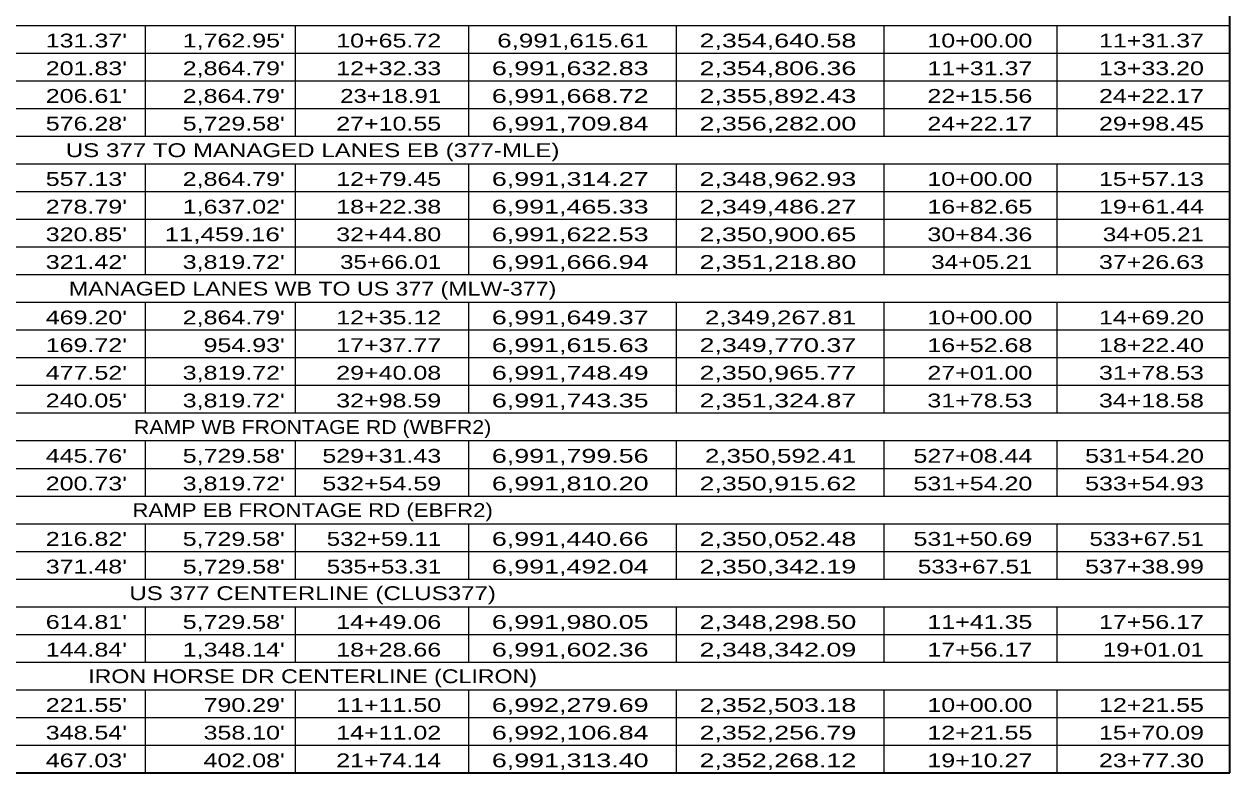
# Model space of a CAD drawing. Extents: x 1953053 to 1967065, y 7363860 to 7371201.
# Drawn here: x 1960635 to 1961680, y 7368112 to 7368761 of the extents above; entities that cross this region are included whole.
import ezdxf
from ezdxf.enums import TextEntityAlignment as Align

# ---------------------------------------------------------------- set-up
doc = ezdxf.new("R2010")
doc.units = 0
doc.header["$LTSCALE"] = 4.8
doc.layers.add('10', color=7, linetype='Continuous')
doc.layers.add('12', color=7, linetype='Continuous', lineweight=25)

msp = doc.modelspace()

# ---------------------------------------------------------------- linework, layer by layer
at = {"layer": '12', "lineweight": 35}
for p, q in [((1961680.213, 7368159.747), (1961680.213, 7370164.879)), ((1961680.213, 7368111.747), (1961680.213, 7370116.879)), ((1959956.881, 7368111.747), (1961680.213, 7368111.747))]:
    msp.add_line(p, q, dxfattribs=at)
at = {"layer": '12', "lineweight": 13}
for p, q in [((1959956.881, 7368759.747), (1961680.213, 7368759.747)), ((1959956.881, 7368735.747), (1961680.213, 7368735.747)), ((1959956.881, 7368711.747), (1961680.213, 7368711.747)), ((1959956.881, 7368687.747), (1961680.213, 7368687.747)), ((1959956.881, 7368663.747), (1961680.213, 7368663.747)), ((1959956.881, 7368639.747), (1961680.213, 7368639.747)), ((1959956.881, 7368615.747), (1961680.213, 7368615.747)), ((1959956.881, 7368591.747), (1961680.213, 7368591.747)), ((1959956.881, 7368567.747), (1961680.213, 7368567.747)), ((1959956.881, 7368543.747), (1961680.213, 7368543.747)), ((1959956.881, 7368519.747), (1961680.213, 7368519.747)), ((1959956.881, 7368495.747), (1961680.213, 7368495.747)), ((1959956.881, 7368471.747), (1961680.213, 7368471.747)), ((1959956.881, 7368447.747), (1961680.213, 7368447.747)), ((1959956.881, 7368423.747), (1961680.213, 7368423.747)), ((1959956.881, 7368399.747), (1961680.213, 7368399.747)), ((1959956.881, 7368375.747), (1961680.213, 7368375.747)), ((1959956.881, 7368351.747), (1961680.213, 7368351.747)), ((1959956.881, 7368327.747), (1961680.213, 7368327.747)), ((1959956.881, 7368303.747), (1961680.213, 7368303.747)), ((1959956.881, 7368279.747), (1961680.213, 7368279.747)), ((1959956.881, 7368255.747), (1961680.213, 7368255.747)), ((1959956.881, 7368231.747), (1961680.213, 7368231.747)), ((1959956.881, 7368207.747), (1961680.213, 7368207.747)), ((1959956.881, 7368207.747), (1961680.213, 7368207.747)), ((1959956.881, 7368183.747), (1961680.213, 7368183.747)), ((1959956.881, 7368183.747), (1961680.213, 7368183.747)), ((1959956.881, 7368159.747), (1961680.213, 7368159.747)), ((1959956.881, 7368135.747), (1961680.213, 7368135.747)), ((1959956.881, 7368111.747), (1961680.213, 7368111.747))]:
    msp.add_line(p, q, dxfattribs=at)
at = {"layer": '12'}
for p, q in [((1960740.213, 7368759.747), (1960740.213, 7368663.747)), ((1960870.213, 7368759.747), (1960870.213, 7368663.747)), ((1961020.213, 7368759.747), (1961020.213, 7368663.747)), ((1961200.213, 7368759.747), (1961200.213, 7368663.747)), ((1961380.213, 7368759.747), (1961380.213, 7368663.747)), ((1961530.213, 7368759.747), (1961530.213, 7368663.747)), ((1960740.213, 7368639.747), (1960740.213, 7368543.747)), ((1960870.213, 7368639.747), (1960870.213, 7368543.747)), ((1961020.213, 7368639.747), (1961020.213, 7368543.747)), ((1961200.213, 7368639.747), (1961200.213, 7368543.747)), ((1961380.213, 7368639.747), (1961380.213, 7368543.747)), ((1961530.213, 7368639.747), (1961530.213, 7368543.747)), ((1960740.213, 7368519.747), (1960740.213, 7368423.747)), ((1960870.213, 7368519.747), (1960870.213, 7368423.747)), ((1961020.213, 7368519.747), (1961020.213, 7368423.747)), ((1961200.213, 7368519.747), (1961200.213, 7368423.747)), ((1961380.213, 7368519.747), (1961380.213, 7368423.747)), ((1961530.213, 7368519.747), (1961530.213, 7368423.747)), ((1960740.213, 7368399.747), (1960740.213, 7368351.747)), ((1960870.213, 7368399.747), (1960870.213, 7368351.747)), ((1961020.213, 7368399.747), (1961020.213, 7368351.747)), ((1961200.213, 7368399.747), (1961200.213, 7368351.747)), ((1961380.213, 7368399.747), (1961380.213, 7368351.747)), ((1961530.213, 7368399.747), (1961530.213, 7368351.747)), ((1960740.213, 7368327.747), (1960740.213, 7368279.747)), ((1960870.213, 7368327.747), (1960870.213, 7368279.747)), ((1961020.213, 7368327.747), (1961020.213, 7368279.747)), ((1961200.213, 7368327.747), (1961200.213, 7368279.747)), ((1961380.213, 7368327.747), (1961380.213, 7368279.747)), ((1961530.213, 7368327.747), (1961530.213, 7368279.747)), ((1960740.213, 7368255.747), (1960740.213, 7368207.747)), ((1960870.213, 7368255.747), (1960870.213, 7368207.747)), ((1961020.213, 7368255.747), (1961020.213, 7368207.747)), ((1961200.213, 7368255.747), (1961200.213, 7368207.747)), ((1961380.213, 7368255.747), (1961380.213, 7368207.747)), ((1961530.213, 7368255.747), (1961530.213, 7368207.747)), ((1960740.213, 7368183.747), (1960740.213, 7368111.747)), ((1960870.213, 7368183.747), (1960870.213, 7368111.747)), ((1961020.213, 7368183.747), (1961020.213, 7368111.747)), ((1961200.213, 7368183.747), (1961200.213, 7368111.747)), ((1961380.213, 7368183.747), (1961380.213, 7368111.747)), ((1961530.213, 7368183.747), (1961530.213, 7368111.747))]:
    msp.add_line(p, q, dxfattribs=at)

# ---------------------------------------------------------------- texts
at = {"layer": '10'}
for s, width, p in [("131.37'", 1.35, (1960724.337, 7368740.574)), ("1,762.95'", 1.35, (1960861.106, 7368740.574)), ('10+65.72', 1.35, (1960996.65, 7368740.574)), ('6,991,615.61', 1.4, (1961176.415, 7368740.574)), ('2,354,640.58', 1.45, (1961356.415, 7368740.574)), ('10+00.00', 1.35, (1961508.993, 7368740.574)), ('11+31.37', 1.35, (1961657.725, 7368740.574)), ("201.83'", 1.35, (1960724.337, 7368716.574)), ("2,864.79'", 1.35, (1960861.106, 7368716.574)), ('12+32.33', 1.35, (1960996.65, 7368716.574)), ('6,991,632.83', 1.45, (1961176.415, 7368716.574)), ('2,354,806.36', 1.45, (1961356.415, 7368716.574)), ('11+31.37', 1.35, (1961508.993, 7368716.574)), ('13+33.20', 1.35, (1961657.725, 7368716.574)), ("206.61'", 1.35, (1960724.337, 7368692.574)), ("2,864.79'", 1.35, (1960861.106, 7368692.574)), ('23+18.91', 1.3, (1960996.65, 7368692.574)), ('6,991,668.72', 1.45, (1961176.415, 7368692.574)), ('2,355,892.43', 1.45, (1961356.415, 7368692.574)), ('22+15.56', 1.35, (1961508.993, 7368692.574)), ('24+22.17', 1.35, (1961657.725, 7368692.574)), ("576.28'", 1.35, (1960724.337, 7368668.574)), ("5,729.58'", 1.35, (1960861.106, 7368668.574)), ('27+10.55', 1.35, (1960996.65, 7368668.574)), ('6,991,709.84', 1.45, (1961176.415, 7368668.574)), ('2,356,282.00', 1.45, (1961356.415, 7368668.574)), ('24+22.17', 1.35, (1961508.993, 7368668.574)), ('29+98.45', 1.35, (1961657.725, 7368668.574)), ("557.13'", 1.35, (1960724.337, 7368620.574)), ("2,864.79'", 1.35, (1960861.106, 7368620.574)), ('12+79.45', 1.35, (1960996.65, 7368620.574)), ('6,991,314.27', 1.45, (1961176.415, 7368620.574)), ('2,348,962.93', 1.45, (1961356.415, 7368620.574)), ('10+00.00', 1.35, (1961508.993, 7368620.574)), ('15+57.13', 1.35, (1961657.725, 7368620.574)), ("278.79'", 1.35, (1960724.337, 7368596.574)), ("1,637.02'", 1.35, (1960861.106, 7368596.574)), ('18+22.38', 1.35, (1960996.65, 7368596.574)), ('6,991,465.33', 1.45, (1961176.415, 7368596.574)), ('2,349,486.27', 1.45, (1961356.415, 7368596.574)), ('16+82.65', 1.35, (1961508.993, 7368596.574)), ('19+61.44', 1.35, (1961657.725, 7368596.574)), ("320.85'", 1.35, (1960724.337, 7368572.574)), ("11,459.16'", 1.4, (1960861.106, 7368572.574)), ('32+44.80', 1.35, (1960996.65, 7368572.574)), ('6,991,622.53', 1.45, (1961176.415, 7368572.574)), ('2,350,900.65', 1.45, (1961356.415, 7368572.574)), ('30+84.36', 1.35, (1961508.993, 7368572.574)), ('34+05.21', 1.3, (1961657.725, 7368572.574)), ("321.42'", 1.35, (1960724.337, 7368548.574)), ("3,819.72'", 1.35, (1960861.106, 7368548.574)), ('35+66.01', 1.3, (1960996.65, 7368548.574)), ('6,991,666.94', 1.45, (1961176.415, 7368548.574)), ('2,351,218.80', 1.45, (1961356.415, 7368548.574)), ('34+05.21', 1.3, (1961508.993, 7368548.574)), ('37+26.63', 1.35, (1961657.725, 7368548.574)), ("469.20'", 1.35, (1960724.337, 7368500.574)), ("2,864.79'", 1.35, (1960861.106, 7368500.574)), ('12+35.12', 1.35, (1960996.65, 7368500.574)), ('6,991,649.37', 1.45, (1961176.415, 7368500.574)), ('2,349,267.81', 1.4, (1961356.415, 7368500.574)), ('10+00.00', 1.35, (1961508.993, 7368500.574)), ('14+69.20', 1.35, (1961657.725, 7368500.574)), ("169.72'", 1.35, (1960724.337, 7368476.574)), ("954.93'", 1.35, (1960861.106, 7368476.574)), ('17+37.77', 1.35, (1960996.65, 7368476.574)), ('6,991,615.63', 1.45, (1961176.415, 7368476.574)), ('2,349,770.37', 1.45, (1961356.415, 7368476.574)), ('16+52.68', 1.35, (1961508.993, 7368476.574)), ('18+22.40', 1.35, (1961657.725, 7368476.574)), ("477.52'", 1.35, (1960724.337, 7368452.574)), ("3,819.72'", 1.35, (1960861.106, 7368452.574)), ('29+40.08', 1.35, (1960996.65, 7368452.574)), ('6,991,748.49', 1.45, (1961176.415, 7368452.574)), ('2,350,965.77', 1.45, (1961356.415, 7368452.574)), ('27+01.00', 1.35, (1961508.993, 7368452.574)), ('31+78.53', 1.35, (1961657.725, 7368452.574)), ("240.05'", 1.35, (1960724.337, 7368428.574)), ("3,819.72'", 1.35, (1960861.106, 7368428.574)), ('32+98.59', 1.35, (1960996.65, 7368428.574)), ('6,991,743.35', 1.45, (1961176.415, 7368428.574)), ('2,351,324.87', 1.45, (1961356.415, 7368428.574)), ('31+78.53', 1.35, (1961508.993, 7368428.574)), ('34+18.58', 1.35, (1961657.725, 7368428.574)), ("445.76'", 1.35, (1960724.337, 7368380.574)), ("5,729.58'", 1.35, (1960861.106, 7368380.574)), ('529+31.43', 1.35, (1960996.65, 7368380.574)), ('6,991,799.56', 1.45, (1961176.415, 7368380.574)), ('2,350,592.41', 1.4, (1961356.415, 7368380.574)), ('527+08.44', 1.35, (1961508.993, 7368380.574)), ('531+54.20', 1.35, (1961657.725, 7368380.574)), ("200.73'", 1.35, (1960724.337, 7368356.574)), ("3,819.72'", 1.35, (1960861.106, 7368356.574)), ('532+54.59', 1.35, (1960996.65, 7368356.574)), ('6,991,810.20', 1.45, (1961176.415, 7368356.574)), ('2,350,915.62', 1.45, (1961356.415, 7368356.574)), ('531+54.20', 1.35, (1961508.993, 7368356.574)), ('533+54.93', 1.35, (1961657.725, 7368356.574)), ("216.82'", 1.35, (1960724.337, 7368308.574)), ("5,729.58'", 1.35, (1960861.106, 7368308.574)), ('532+59.11', 1.3, (1960996.65, 7368308.574)), ('6,991,440.66', 1.45, (1961176.415, 7368308.574)), ('2,350,052.48', 1.45, (1961356.415, 7368308.574)), ('531+50.69', 1.35, (1961508.993, 7368308.574)), ('533+67.51', 1.3, (1961657.725, 7368308.574)), ("371.48'", 1.35, (1960724.337, 7368284.574)), ("5,729.58'", 1.35, (1960861.106, 7368284.574)), ('535+53.31', 1.3, (1960996.65, 7368284.574)), ('6,991,492.04', 1.45, (1961176.415, 7368284.574)), ('2,350,342.19', 1.45, (1961356.415, 7368284.574)), ('533+67.51', 1.3, (1961508.993, 7368284.574)), ('537+38.99', 1.35, (1961657.725, 7368284.574)), ("614.81'", 1.35, (1960724.337, 7368236.574)), ("5,729.58'", 1.35, (1960861.106, 7368236.574)), ('14+49.06', 1.35, (1960996.65, 7368236.574)), ('6,991,980.05', 1.45, (1961176.415, 7368236.574)), ('2,348,298.50', 1.45, (1961356.415, 7368236.574)), ('11+41.35', 1.35, (1961508.993, 7368236.574)), ('17+56.17', 1.35, (1961657.725, 7368236.574)), ("144.84'", 1.35, (1960724.337, 7368212.574)), ("1,348.14'", 1.35, (1960861.106, 7368212.574)), ('18+28.66', 1.35, (1960996.65, 7368212.574)), ('6,991,602.36', 1.45, (1961176.415, 7368212.574)), ('2,348,342.09', 1.45, (1961356.415, 7368212.574)), ('17+56.17', 1.35, (1961508.993, 7368212.574)), ('19+01.01', 1.3, (1961657.725, 7368212.574)), ("221.55'", 1.35, (1960724.337, 7368164.574)), ("790.29'", 1.35, (1960861.106, 7368164.574)), ('11+11.50', 1.35, (1960996.65, 7368164.574)), ('6,992,279.69', 1.45, (1961176.415, 7368164.574)), ('2,352,503.18', 1.45, (1961356.415, 7368164.574)), ('10+00.00', 1.35, (1961508.993, 7368164.574)), ('12+21.55', 1.35, (1961657.725, 7368164.574)), ("348.54'", 1.35, (1960724.337, 7368140.574)), ("358.10'", 1.35, (1960861.106, 7368140.574)), ('14+11.02', 1.35, (1960996.65, 7368140.574)), ('6,992,106.84', 1.45, (1961176.415, 7368140.574)), ('2,352,256.79', 1.45, (1961356.415, 7368140.574)), ('12+21.55', 1.35, (1961508.993, 7368140.574)), ('15+70.09', 1.35, (1961657.725, 7368140.574)), ("467.03'", 1.35, (1960724.337, 7368116.574)), ("402.08'", 1.35, (1960861.106, 7368116.574)), ('21+74.14', 1.35, (1960996.65, 7368116.574)), ('6,991,313.40', 1.45, (1961176.415, 7368116.574)), ('2,352,268.12', 1.45, (1961356.415, 7368116.574)), ('19+10.27', 1.35, (1961508.993, 7368116.574)), ('23+77.30', 1.35, (1961657.725, 7368116.574))]:
    msp.add_text(s, height=12, dxfattribs=dict(at, width=width)).set_placement(p, align=Align.RIGHT)
for s, width, p in [('US 377 TO MANAGED LANES EB (377-MLE)', 1.3, (1960885.213, 7368645.541)), ('MANAGED LANES WB TO US 377 (MLW-377)', 1.25, (1960885.213, 7368525.541)), ('RAMP WB FRONTAGE RD (WBFR2)', 1.15, (1960885.213, 7368405.541)), ('RAMP EB FRONTAGE RD (EBFR2)', 1.2, (1960885.213, 7368333.541)), ('US 377 CENTERLINE (CLUS377)', 1.3, (1960885.214, 7368261.541)), ('IRON HORSE DR CENTERLINE (CLIRON)', 1.25, (1960885.213, 7368189.541))]:
    msp.add_text(s, height=12, dxfattribs=dict(at, width=width)).set_placement(p, align=Align.CENTER)

doc.saveas('drawing.dxf')
